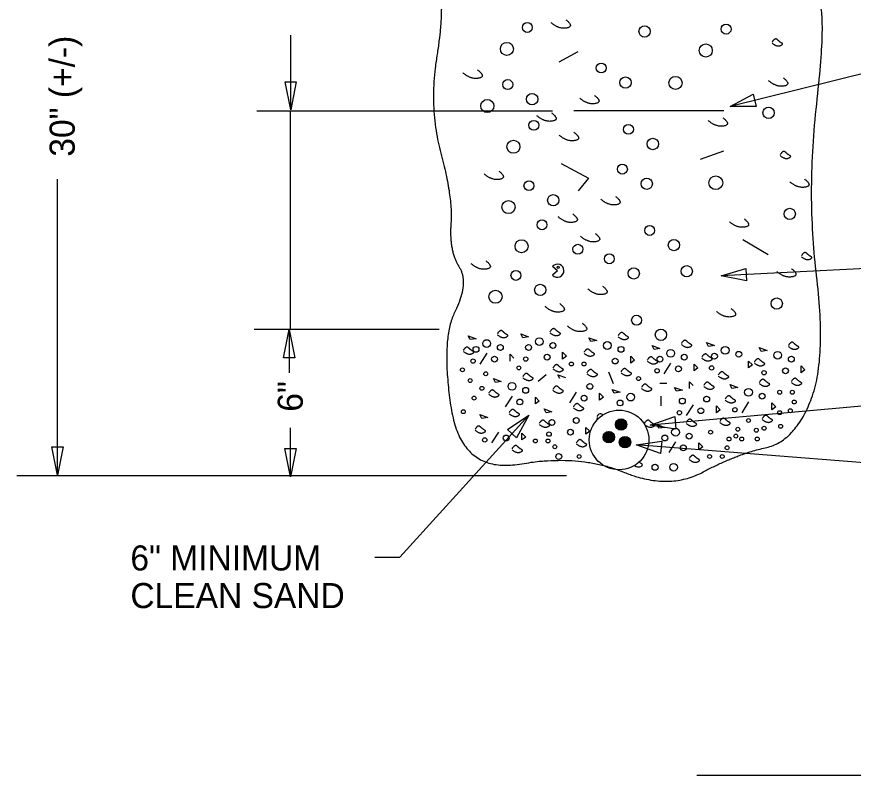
# Model space of a CAD drawing. Extents: x 10310.4 to 10401.1, y 10100.5 to 10143.6.
# Drawn here: x 10316.47 to 10338.7, y 10102.81 to 10122.98 of the extents above; entities that cross this region are included whole.
import ezdxf

# ---------------------------------------------------------------- set-up
doc = ezdxf.new("R2010")
doc.units = 0
for name, color, linetype in [('G-ANNO-TEXT', 7, 'Continuous'), ('G-DETL-LINE', 7, 'Continuous'), ('G-DETL-OTLN', 7, 'Continuous'), ('G-DETL-PATT', 7, 'Continuous')]:
    doc.layers.add(name, color=color, linetype=linetype)

msp = doc.modelspace()

# ---------------------------------------------------------------- linework, layer by layer
at = {"layer": 'G-ANNO-TEXT'}
for p, q in [((10349.089, 10123.964), (10335.433, 10120.592)), ((10323.748, 10120.498), (10323.748, 10122.486)), ((10330.708, 10120.468), (10322.853, 10120.468)), ((10323.734, 10120.468), (10323.734, 10114.663)), ((10317.554, 10110.793), (10317.554, 10118.66)), ((10347.769, 10116.722), (10335.191, 10116.085)), ((10327.698, 10114.663), (10322.78, 10114.663)), ((10323.708, 10114.66), (10323.708, 10113.514)), ((10348.599, 10113.478), (10333.307, 10112.124)), ((10326.648, 10108.611), (10330.078, 10112.388)), ((10323.747, 10110.75), (10323.747, 10112.051)), ((10350.535, 10110.217), (10332.93, 10111.596)), ((10331.075, 10110.77), (10316.467, 10110.77)), ((10325.981, 10108.611), (10326.648, 10108.611)), ((10334.547, 10102.814), (10373.072, 10102.814))]:
    msp.add_line(p, q, dxfattribs=at)
for points in [[(10323.898, 10121.248), (10323.748, 10120.498), (10323.598, 10121.248)], [(10336.12, 10120.59), (10335.433, 10120.592), (10336.04, 10120.913)], [(10335.866, 10115.952), (10335.191, 10116.085), (10335.849, 10116.285)], [(10323.558, 10113.91), (10323.708, 10114.66), (10323.858, 10113.91)], [(10329.507, 10112.007), (10330.078, 10112.388), (10329.753, 10111.783)], [(10333.986, 10112.017), (10333.307, 10112.124), (10333.956, 10112.349)], [(10333.576, 10111.363), (10332.93, 10111.596), (10333.61, 10111.695)], [(10317.704, 10111.543), (10317.554, 10110.793), (10317.404, 10111.543)], [(10323.897, 10111.5), (10323.747, 10110.75), (10323.597, 10111.5)]]:
    msp.add_lwpolyline(points, close=True, dxfattribs=at)
at = {"layer": 'G-DETL-LINE'}
msp.add_open_spline([(10327.629, 10127.469), (10327.521, 10124.332), (10327.845, 10123.251), (10327.413, 10120.548), (10328.061, 10118.17), (10327.953, 10116.764), (10328.493, 10115.899), (10327.737, 10114.386), (10328.277, 10110.818), (10331.41, 10111.359), (10333.786, 10110.385), (10335.622, 10111.359), (10337.135, 10111.683), (10337.999, 10113.845), (10337.459, 10118.278), (10337.999, 10123.035), (10337.567, 10123.792), (10338.215, 10124.332), (10337.891, 10127.143)], degree=2, dxfattribs=at)
at = {"layer": 'G-DETL-OTLN'}
msp.add_lwpolyline([(10331.274, 10120.481), (10335.26, 10120.481)], dxfattribs=at)
for centre, radius in [((10332.476, 10111.726), 0.792), ((10332.529, 10112.138), 0.152), ((10332.529, 10112.138), 0.145), ((10332.529, 10112.138), 0.137), ((10332.529, 10112.138), 0.137), ((10332.529, 10112.138), 0.137), ((10332.529, 10112.138), 0.129), ((10332.529, 10112.138), 0.122), ((10332.529, 10112.138), 0.122), ((10332.529, 10112.138), 0.122), ((10332.529, 10112.138), 0.122), ((10332.529, 10112.138), 0.114), ((10332.529, 10112.138), 0.106), ((10332.529, 10112.138), 0.106), ((10332.529, 10112.138), 0.0988), ((10332.529, 10112.138), 0.0911), ((10332.529, 10112.138), 0.0911), ((10332.529, 10112.138), 0.0835), ((10332.529, 10112.138), 0.0758), ((10332.529, 10112.138), 0.0758), ((10332.529, 10112.138), 0.0682), ((10332.529, 10112.138), 0.0605), ((10332.529, 10112.138), 0.0605), ((10332.529, 10112.138), 0.0605), ((10332.529, 10112.138), 0.0529), ((10332.529, 10112.138), 0.0452), ((10332.529, 10112.138), 0.0452), ((10332.529, 10112.138), 0.0452), ((10332.529, 10112.138), 0.0452), ((10332.529, 10112.138), 0.0376), ((10332.529, 10112.138), 0.0299), ((10332.529, 10112.138), 0.0223), ((10332.529, 10112.138), 0.0146), ((10332.529, 10112.138), 0.0146), ((10332.529, 10112.138), 0.00695), ((10332.204, 10111.802), 0.152), ((10332.204, 10111.802), 0.145), ((10332.204, 10111.802), 0.137), ((10332.204, 10111.802), 0.137), ((10332.204, 10111.802), 0.137), ((10332.204, 10111.802), 0.129), ((10332.204, 10111.802), 0.122), ((10332.204, 10111.802), 0.122), ((10332.204, 10111.802), 0.122), ((10332.204, 10111.802), 0.122), ((10332.204, 10111.802), 0.114), ((10332.204, 10111.802), 0.106), ((10332.204, 10111.802), 0.106), ((10332.204, 10111.802), 0.0988), ((10332.204, 10111.802), 0.0911), ((10332.204, 10111.802), 0.0911), ((10332.204, 10111.802), 0.0835), ((10332.204, 10111.802), 0.0758), ((10332.204, 10111.802), 0.0758), ((10332.204, 10111.802), 0.0682), ((10332.204, 10111.802), 0.0605), ((10332.204, 10111.802), 0.0605), ((10332.204, 10111.802), 0.0605), ((10332.204, 10111.802), 0.0529), ((10332.204, 10111.802), 0.0452), ((10332.204, 10111.802), 0.0452), ((10332.204, 10111.802), 0.0452), ((10332.204, 10111.802), 0.0452), ((10332.204, 10111.802), 0.0376), ((10332.204, 10111.802), 0.0299), ((10332.204, 10111.802), 0.0223), ((10332.204, 10111.802), 0.0146), ((10332.204, 10111.802), 0.0146), ((10332.204, 10111.802), 0.00695), ((10332.633, 10111.668), 0.152), ((10332.633, 10111.668), 0.145), ((10332.633, 10111.668), 0.137), ((10332.633, 10111.668), 0.137), ((10332.633, 10111.668), 0.137), ((10332.633, 10111.668), 0.129), ((10332.633, 10111.668), 0.122), ((10332.633, 10111.668), 0.122), ((10332.633, 10111.668), 0.122), ((10332.633, 10111.668), 0.122), ((10332.633, 10111.668), 0.114), ((10332.633, 10111.668), 0.106), ((10332.633, 10111.668), 0.106), ((10332.633, 10111.668), 0.0988), ((10332.633, 10111.668), 0.0911), ((10332.633, 10111.668), 0.0911), ((10332.633, 10111.668), 0.0835), ((10332.633, 10111.668), 0.0758), ((10332.633, 10111.668), 0.0758), ((10332.633, 10111.668), 0.0682), ((10332.633, 10111.668), 0.0605), ((10332.633, 10111.668), 0.0605), ((10332.633, 10111.668), 0.0605), ((10332.633, 10111.668), 0.0529), ((10332.633, 10111.668), 0.0452), ((10332.633, 10111.668), 0.0452), ((10332.633, 10111.668), 0.0452), ((10332.633, 10111.668), 0.0452), ((10332.633, 10111.668), 0.0376), ((10332.633, 10111.668), 0.0299), ((10332.633, 10111.668), 0.0223), ((10332.633, 10111.668), 0.0146), ((10332.633, 10111.668), 0.0146), ((10332.633, 10111.668), 0.00695)]:
    msp.add_circle(centre, radius, dxfattribs=at)
at = {"layer": 'G-DETL-PATT'}
for p, q in [((10330.881, 10121.774), (10331.386, 10122.055)), ((10334.642, 10119.189), (10335.26, 10119.414)), ((10330.937, 10119.077), (10331.667, 10118.683)), ((10331.667, 10118.683), (10331.386, 10118.346)), ((10335.765, 10117.054), (10336.439, 10116.66)), ((10330.838, 10116.225), (10330.707, 10116.341)), ((10330.838, 10116.225), (10330.711, 10116.107)), ((10329.916, 10114.444), (10329.864, 10114.548)), ((10329.864, 10114.548), (10330.071, 10114.47)), ((10328.519, 10114.393), (10328.468, 10114.496)), ((10328.468, 10114.496), (10328.674, 10114.418)), ((10328.674, 10114.418), (10328.519, 10114.393)), ((10330.071, 10114.47), (10329.916, 10114.444)), ((10331.727, 10114.341), (10331.675, 10114.444)), ((10331.675, 10114.444), (10331.882, 10114.367)), ((10331.882, 10114.367), (10331.727, 10114.341)), ((10334.856, 10114.211), (10334.804, 10114.315)), ((10334.804, 10114.315), (10335.011, 10114.237)), ((10333.408, 10114.134), (10333.356, 10114.237)), ((10333.356, 10114.237), (10333.563, 10114.16)), ((10333.563, 10114.16), (10333.408, 10114.134)), ((10335.011, 10114.237), (10334.856, 10114.211)), ((10336.253, 10114.082), (10336.201, 10114.185)), ((10336.201, 10114.185), (10336.408, 10114.108)), ((10336.408, 10114.108), (10336.253, 10114.082)), ((10328.959, 10114.03), (10328.778, 10113.745)), ((10329.58, 10113.823), (10329.58, 10114.004)), ((10329.58, 10114.004), (10329.683, 10113.901)), ((10330.976, 10113.875), (10330.976, 10114.056)), ((10330.976, 10114.056), (10331.08, 10113.952)), ((10331.08, 10113.952), (10330.976, 10113.875)), ((10332.787, 10113.771), (10332.787, 10113.952)), ((10332.787, 10113.952), (10332.89, 10113.849)), ((10332.89, 10113.849), (10332.787, 10113.771)), ((10333.847, 10113.771), (10333.666, 10113.486)), ((10334.468, 10113.564), (10334.468, 10113.745)), ((10334.468, 10113.745), (10334.572, 10113.642)), ((10334.572, 10113.642), (10334.468, 10113.564)), ((10335.917, 10113.642), (10335.917, 10113.823)), ((10335.917, 10113.823), (10336.02, 10113.719)), ((10336.02, 10113.719), (10335.917, 10113.642)), ((10337.313, 10113.512), (10337.313, 10113.694)), ((10337.313, 10113.694), (10337.417, 10113.59)), ((10330.537, 10113.461), (10330.33, 10113.279)), ((10330.899, 10113.357), (10330.847, 10113.461)), ((10330.847, 10113.461), (10331.054, 10113.383)), ((10332.192, 10113.538), (10332.321, 10113.228)), ((10337.417, 10113.59), (10337.313, 10113.512)), ((10329.192, 10113.253), (10329.14, 10113.357)), ((10329.14, 10113.357), (10329.347, 10113.279)), ((10329.347, 10113.279), (10329.192, 10113.253)), ((10333.744, 10113.228), (10333.563, 10113.228)), ((10334.344, 10113.093), (10334.344, 10113.274)), ((10334.344, 10113.274), (10334.447, 10113.171)), ((10335.477, 10113.098), (10335.425, 10113.202)), ((10335.425, 10113.202), (10335.632, 10113.124)), ((10331.339, 10112.994), (10331.158, 10112.71)), ((10331.959, 10112.787), (10331.959, 10112.969)), ((10331.959, 10112.969), (10332.063, 10112.865)), ((10332.296, 10113.072), (10332.502, 10112.994)), ((10332.347, 10112.969), (10332.296, 10113.072)), ((10332.502, 10112.994), (10332.347, 10112.969)), ((10334.003, 10113.02), (10333.951, 10113.124)), ((10333.951, 10113.124), (10334.158, 10113.046)), ((10334.158, 10113.046), (10334.003, 10113.02)), ((10335.632, 10113.124), (10335.477, 10113.098)), ((10329.631, 10112.891), (10329.45, 10112.606)), ((10330.252, 10112.684), (10330.252, 10112.865)), ((10330.252, 10112.865), (10330.356, 10112.761)), ((10330.356, 10112.761), (10330.252, 10112.684)), ((10332.063, 10112.865), (10331.959, 10112.787)), ((10333.589, 10112.891), (10333.589, 10112.632)), ((10330.537, 10112.451), (10330.485, 10112.554)), ((10330.485, 10112.554), (10330.692, 10112.477)), ((10334.442, 10112.658), (10334.261, 10112.373)), ((10335.063, 10112.451), (10335.063, 10112.632)), ((10335.063, 10112.632), (10335.167, 10112.528)), ((10335.167, 10112.528), (10335.063, 10112.451)), ((10335.917, 10112.736), (10335.736, 10112.451)), ((10336.537, 10112.528), (10336.537, 10112.71)), ((10336.537, 10112.71), (10336.641, 10112.606)), ((10336.641, 10112.606), (10336.537, 10112.528)), ((10328.83, 10112.295), (10328.778, 10112.399)), ((10328.778, 10112.399), (10328.985, 10112.321)), ((10328.985, 10112.321), (10328.83, 10112.295)), ((10330.692, 10112.477), (10330.537, 10112.451)), ((10333.537, 10112.037), (10333.485, 10112.14)), ((10333.485, 10112.14), (10333.692, 10112.062)), ((10329.269, 10111.933), (10329.088, 10111.648)), ((10329.89, 10111.726), (10329.89, 10111.907)), ((10329.89, 10111.907), (10329.994, 10111.804)), ((10331.597, 10111.881), (10331.597, 10112.062)), ((10331.597, 10112.062), (10331.701, 10111.959)), ((10331.701, 10111.959), (10331.597, 10111.881)), ((10333.692, 10112.062), (10333.537, 10112.037)), ((10329.994, 10111.804), (10329.89, 10111.726)), ((10333.977, 10111.674), (10333.796, 10111.389)), ((10334.598, 10111.467), (10334.598, 10111.648)), ((10334.598, 10111.648), (10334.701, 10111.545)), ((10334.701, 10111.545), (10334.598, 10111.467))]:
    msp.add_line(p, q, dxfattribs=at)
for points in [[(10332.049, 10112.393), (10332.037, 10112.402), (10332.015, 10112.415), (10331.992, 10112.422), (10331.967, 10112.422), (10331.941, 10112.411), (10331.914, 10112.386), (10331.885, 10112.346)], [(10331.885, 10112.321), (10331.923, 10112.294)], [(10332.883, 10111.048), (10332.885, 10111.046), (10332.928, 10111.025), (10332.967, 10111.014), (10333.001, 10111.011), (10333.03, 10111.014), (10333.054, 10111.021), (10333.073, 10111.031), (10333.087, 10111.042), (10333.094, 10111.052), (10333.097, 10111.061), (10333.094, 10111.071), (10333.088, 10111.08), (10333.077, 10111.09), (10333.064, 10111.101), (10333.048, 10111.114), (10333.031, 10111.128), (10333.012, 10111.144)]]:
    msp.add_lwpolyline(points, dxfattribs=at)
for centre, radius in [((10330.038, 10122.69), 0.132), ((10335.322, 10122.646), 0.132), ((10333.156, 10122.584), 0.151), ((10329.495, 10122.12), 0.174), ((10334.779, 10122.077), 0.174), ((10332.001, 10121.613), 0.132), ((10329.518, 10121.173), 0.132), ((10332.648, 10121.224), 0.151), ((10333.976, 10121.216), 0.174), ((10328.975, 10120.603), 0.174), ((10330.165, 10120.784), 0.151), ((10336.45, 10120.422), 0.151), ((10330.211, 10120.089), 0.132), ((10332.726, 10119.982), 0.132), ((10329.668, 10119.519), 0.174), ((10333.372, 10119.593), 0.151), ((10332.564, 10118.925), 0.132), ((10335.047, 10118.563), 0.183), ((10330.081, 10118.485), 0.132), ((10333.211, 10118.537), 0.151), ((10329.538, 10117.916), 0.174), ((10330.728, 10118.097), 0.151), ((10337.013, 10117.734), 0.151), ((10330.428, 10117.445), 0.132), ((10333.289, 10117.294), 0.132), ((10329.885, 10116.875), 0.174), ((10333.935, 10116.906), 0.151), ((10331.381, 10116.795), 0.132), ((10332.218, 10116.541), 0.132), ((10330.859, 10116.315), 0.0274), ((10332.865, 10116.153), 0.151), ((10334.275, 10116.209), 0.151), ((10329.735, 10116.101), 0.132), ((10330.382, 10115.713), 0.151), ((10329.192, 10115.532), 0.174), ((10336.667, 10115.35), 0.151), ((10332.942, 10114.91), 0.132), ((10333.589, 10114.522), 0.151), ((10328.959, 10114.289), 0.103), ((10330.356, 10114.341), 0.103), ((10330.718, 10114.237), 0.0776), ((10332.166, 10114.237), 0.103), ((10328.674, 10114.134), 0.0776), ((10329.321, 10114.185), 0.0776), ((10330.071, 10114.185), 0.0776), ((10332.528, 10114.134), 0.0776), ((10333.847, 10114.03), 0.103), ((10335.296, 10114.108), 0.103), ((10335.658, 10114.004), 0.0776), ((10336.693, 10113.978), 0.103), ((10328.597, 10113.823), 0.0578), ((10329.166, 10113.875), 0.0776), ((10329.994, 10113.875), 0.0578), ((10330.563, 10113.927), 0.0776), ((10332.373, 10113.823), 0.0776), ((10333.563, 10113.875), 0.0776), ((10334.21, 10113.927), 0.0776), ((10335.011, 10113.952), 0.0776), ((10337.055, 10113.875), 0.0776), ((10328.312, 10113.59), 0.0517), ((10329.813, 10113.642), 0.0517), ((10331.209, 10113.745), 0.0517), ((10331.545, 10113.745), 0.0517), ((10334.054, 10113.616), 0.0776), ((10334.934, 10113.642), 0.0578), ((10336.9, 10113.564), 0.0776), ((10328.933, 10113.486), 0.0517), ((10333.485, 10113.564), 0.0578), ((10336.331, 10113.512), 0.0578), ((10328.519, 10113.305), 0.0517), ((10329.631, 10113.15), 0.103), ((10331.701, 10113.15), 0.0776), ((10332.994, 10113.357), 0.0517), ((10328.83, 10113.098), 0.0517), ((10329.994, 10113.046), 0.0776), ((10332.787, 10112.865), 0.103), ((10335.917, 10112.994), 0.103), ((10336.279, 10112.891), 0.0776), ((10336.744, 10112.994), 0.0517), ((10337.081, 10112.994), 0.0517), ((10328.623, 10112.839), 0.0517), ((10329.838, 10112.736), 0.0776), ((10331.545, 10112.839), 0.0776), ((10332.502, 10112.71), 0.0776), ((10334.158, 10112.761), 0.0776), ((10334.804, 10112.813), 0.0776), ((10337.132, 10112.736), 0.0517), ((10328.338, 10112.477), 0.0517), ((10334.649, 10112.503), 0.0776), ((10335.555, 10112.528), 0.0578), ((10337.029, 10112.503), 0.0517), ((10331.339, 10112.244), 0.0776), ((10334.08, 10112.451), 0.0578), ((10336.744, 10112.451), 0.0517), ((10330.692, 10112.192), 0.0776), ((10335.917, 10112.244), 0.0517), ((10336.331, 10112.037), 0.0517), ((10336.77, 10112.088), 0.0517), ((10329.476, 10111.778), 0.0776), ((10330.614, 10111.881), 0.0578), ((10331.183, 10111.933), 0.0776), ((10333.692, 10111.778), 0.0776), ((10333.977, 10111.933), 0.103), ((10334.339, 10111.829), 0.0776), ((10334.908, 10111.933), 0.0517), ((10335.58, 10111.829), 0.0517), ((10335.632, 10112.011), 0.0517), ((10336.124, 10111.985), 0.0517), ((10328.907, 10111.726), 0.0578), ((10330.252, 10111.7), 0.0517), ((10330.588, 10111.7), 0.0517), ((10335.399, 10111.752), 0.0517), ((10335.736, 10111.752), 0.0517), ((10336.149, 10111.752), 0.0517), ((10330.77, 10111.545), 0.0517), ((10334.184, 10111.519), 0.0776), ((10335.348, 10111.519), 0.0517), ((10330.873, 10111.286), 0.0776), ((10331.416, 10111.286), 0.0517), ((10334.882, 10111.286), 0.0517), ((10335.218, 10111.286), 0.0517), ((10333.434, 10111.001), 0.0818), ((10333.925, 10111.001), 0.103)]:
    msp.add_circle(centre, radius, dxfattribs=at)
msp.add_arc((10330.838, 10116.225), 0.174, 223.1288, 138.4277, dxfattribs=at)
for points in [[(10331.061, 10122.895), (10331.293, 10122.714), (10330.88, 10122.636), (10330.673, 10122.817)], [(10336.544, 10122.273), (10336.673, 10122.17), (10336.854, 10122.248), (10336.751, 10122.299), (10336.622, 10122.429), (10336.544, 10122.299)], [(10328.717, 10121.561), (10328.949, 10121.38), (10328.536, 10121.302), (10328.329, 10121.483)], [(10336.838, 10121.354), (10337.071, 10121.173), (10336.657, 10121.095), (10336.45, 10121.276)], [(10331.82, 10120.888), (10332.053, 10120.707), (10331.639, 10120.629), (10331.432, 10120.81)], [(10330.682, 10120.422), (10330.915, 10120.241), (10330.501, 10120.163), (10330.294, 10120.344)], [(10335.235, 10120.292), (10335.467, 10120.111), (10335.054, 10120.033), (10334.847, 10120.215)], [(10331.277, 10119.904), (10331.51, 10119.723), (10331.096, 10119.645), (10330.889, 10119.826)], [(10336.761, 10119.283), (10336.89, 10119.179), (10337.071, 10119.257), (10336.968, 10119.309), (10336.838, 10119.438), (10336.761, 10119.309)], [(10329.28, 10118.874), (10329.512, 10118.692), (10329.099, 10118.615), (10328.892, 10118.796)], [(10337.401, 10118.666), (10337.634, 10118.485), (10337.22, 10118.408), (10337.013, 10118.589)], [(10332.383, 10118.2), (10332.616, 10118.019), (10332.202, 10117.942), (10331.995, 10118.123)], [(10331.245, 10117.734), (10331.478, 10117.553), (10331.064, 10117.476), (10330.857, 10117.657)], [(10335.798, 10117.605), (10336.03, 10117.424), (10335.617, 10117.346), (10335.41, 10117.527)], [(10331.84, 10117.217), (10332.073, 10117.035), (10331.659, 10116.958), (10331.452, 10117.139)], [(10337.324, 10116.595), (10337.453, 10116.492), (10337.634, 10116.569), (10337.531, 10116.621), (10337.401, 10116.751), (10337.324, 10116.621)], [(10328.933, 10116.49), (10329.166, 10116.308), (10328.752, 10116.231), (10328.545, 10116.412)], [(10337.055, 10116.283), (10337.288, 10116.101), (10336.874, 10116.024), (10336.667, 10116.205)], [(10332.037, 10115.817), (10332.27, 10115.635), (10331.856, 10115.558), (10331.649, 10115.739)], [(10330.899, 10115.35), (10331.132, 10115.169), (10330.718, 10115.092), (10330.511, 10115.273)], [(10335.451, 10115.221), (10335.684, 10115.04), (10335.27, 10114.962), (10335.063, 10115.143)], [(10331.494, 10114.833), (10331.727, 10114.651), (10331.313, 10114.574), (10331.106, 10114.755)], [(10329.244, 10114.522), (10329.373, 10114.418), (10329.554, 10114.496), (10329.45, 10114.548), (10329.321, 10114.677), (10329.244, 10114.548)], [(10330.64, 10114.574), (10330.77, 10114.47), (10330.951, 10114.548), (10330.847, 10114.6), (10330.718, 10114.729), (10330.64, 10114.6)], [(10332.451, 10114.47), (10332.58, 10114.367), (10332.761, 10114.444), (10332.658, 10114.496), (10332.528, 10114.626), (10332.451, 10114.496)], [(10334.132, 10114.263), (10334.261, 10114.16), (10334.442, 10114.237), (10334.339, 10114.289), (10334.21, 10114.418), (10334.132, 10114.289)], [(10336.977, 10114.211), (10337.106, 10114.108), (10337.288, 10114.185), (10337.184, 10114.237), (10337.055, 10114.367), (10336.977, 10114.237)], [(10328.338, 10114.082), (10328.468, 10113.978), (10328.649, 10114.056), (10328.545, 10114.108), (10328.416, 10114.237), (10328.338, 10114.108)], [(10331.545, 10114.03), (10331.675, 10113.927), (10331.856, 10114.004), (10331.752, 10114.056), (10331.623, 10114.185), (10331.545, 10114.056)], [(10333.227, 10113.823), (10333.356, 10113.719), (10333.537, 10113.797), (10333.434, 10113.849), (10333.304, 10113.978), (10333.227, 10113.849)], [(10334.675, 10113.901), (10334.804, 10113.797), (10334.986, 10113.875), (10334.882, 10113.927), (10334.753, 10114.056), (10334.675, 10113.927)], [(10336.072, 10113.771), (10336.201, 10113.668), (10336.382, 10113.745), (10336.279, 10113.797), (10336.149, 10113.927), (10336.072, 10113.797)], [(10330.718, 10113.616), (10330.847, 10113.512), (10331.028, 10113.59), (10330.925, 10113.642), (10330.795, 10113.771), (10330.718, 10113.642)], [(10329.916, 10113.383), (10330.045, 10113.279), (10330.226, 10113.357), (10330.123, 10113.409), (10329.994, 10113.538), (10329.916, 10113.409)], [(10331.623, 10113.486), (10331.752, 10113.383), (10331.933, 10113.461), (10331.83, 10113.512), (10331.701, 10113.642), (10331.623, 10113.512)], [(10332.528, 10113.512), (10332.658, 10113.409), (10332.839, 10113.486), (10332.735, 10113.538), (10332.606, 10113.668), (10332.528, 10113.538)], [(10335.114, 10113.426), (10335.243, 10113.322), (10335.424, 10113.4), (10335.321, 10113.452), (10335.192, 10113.581), (10335.114, 10113.452)], [(10333.072, 10113.098), (10333.201, 10112.994), (10333.382, 10113.072), (10333.278, 10113.124), (10333.149, 10113.253), (10333.072, 10113.124)], [(10334.727, 10113.15), (10334.856, 10113.046), (10335.037, 10113.124), (10334.934, 10113.176), (10334.804, 10113.305), (10334.727, 10113.176)], [(10336.201, 10113.228), (10336.331, 10113.124), (10336.512, 10113.202), (10336.408, 10113.253), (10336.279, 10113.383), (10336.201, 10113.253)], [(10337.055, 10113.253), (10337.184, 10113.15), (10337.365, 10113.228), (10337.262, 10113.279), (10337.132, 10113.409), (10337.055, 10113.279)], [(10329.011, 10112.943), (10329.14, 10112.839), (10329.321, 10112.917), (10329.218, 10112.969), (10329.088, 10113.098), (10329.011, 10112.969)], [(10330.718, 10113.046), (10330.847, 10112.943), (10331.028, 10113.02), (10330.925, 10113.072), (10330.795, 10113.202), (10330.718, 10113.072)], [(10335.296, 10112.787), (10335.425, 10112.684), (10335.606, 10112.761), (10335.503, 10112.813), (10335.374, 10112.943), (10335.296, 10112.813)], [(10329.554, 10112.425), (10329.683, 10112.321), (10329.864, 10112.399), (10329.761, 10112.451), (10329.631, 10112.58), (10329.554, 10112.451)], [(10331.261, 10112.58), (10331.39, 10112.477), (10331.571, 10112.554), (10331.468, 10112.606), (10331.339, 10112.736), (10331.261, 10112.606)], [(10335.154, 10112.192), (10335.284, 10112.088), (10335.465, 10112.166), (10335.361, 10112.218), (10335.232, 10112.347), (10335.154, 10112.218)], [(10336.279, 10112.27), (10336.408, 10112.166), (10336.589, 10112.244), (10336.486, 10112.295), (10336.356, 10112.425), (10336.279, 10112.295)], [(10328.649, 10111.985), (10328.778, 10111.881), (10328.959, 10111.959), (10328.856, 10112.011), (10328.726, 10112.14), (10328.649, 10112.011)], [(10330.356, 10112.14), (10330.485, 10112.037), (10330.666, 10112.114), (10330.563, 10112.166), (10330.433, 10112.295), (10330.356, 10112.166)], [(10333.149, 10112.14), (10333.278, 10112.037), (10333.46, 10112.114), (10333.356, 10112.166), (10333.227, 10112.295), (10333.149, 10112.166)], [(10334.261, 10112.166), (10334.391, 10112.062), (10334.572, 10112.14), (10334.468, 10112.192), (10334.339, 10112.321), (10334.261, 10112.192)], [(10331.339, 10111.622), (10331.468, 10111.519), (10331.649, 10111.596), (10331.545, 10111.648), (10331.416, 10111.778), (10331.339, 10111.648)], [(10329.631, 10111.467), (10329.761, 10111.363), (10329.942, 10111.441), (10329.838, 10111.493), (10329.709, 10111.622), (10329.631, 10111.493)], [(10334.339, 10111.208), (10334.468, 10111.105), (10334.649, 10111.182), (10334.546, 10111.234), (10334.417, 10111.363), (10334.339, 10111.234)]]:
    msp.add_open_spline(points, degree=2, dxfattribs=at)

# ---------------------------------------------------------------- texts
at = {"layer": 'G-ANNO-TEXT'}
for s, p in [('30" (+/-)', (10318.008, 10119.256)), ('6"', (10324.07, 10112.478))]:
    msp.add_text(s, height=0.6667, rotation=90, dxfattribs=at).set_placement(p)
for s, p in [('6" MINIMUM', (10319.488, 10108.257)), ('CLEAN SAND', (10319.488, 10107.257))]:
    msp.add_text(s, height=0.6667, dxfattribs=at).set_placement(p)

doc.saveas('drawing.dxf')
